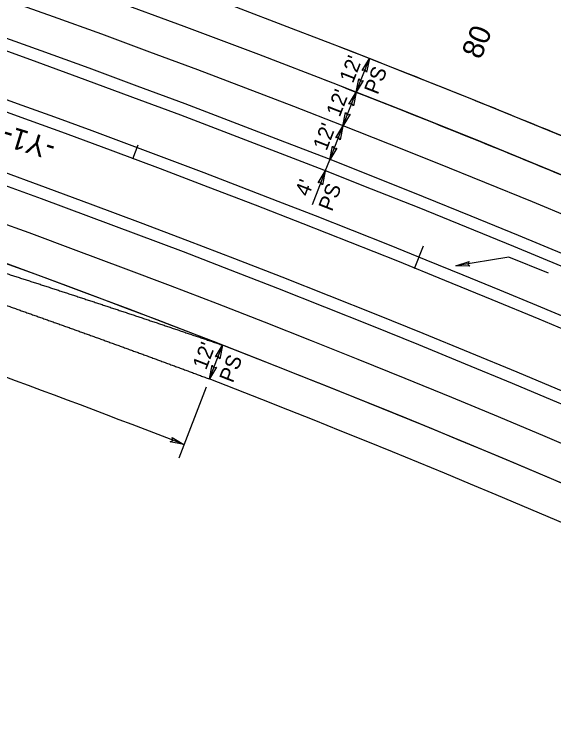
# Model space of a CAD drawing. Extents: x 2389694 to 2405615, y 547005 to 573532.
# Drawn here: x 2396125.1 to 2396303.6, y 553822.6 to 554061.5 of the extents above; entities that cross this region are included whole.
import ezdxf

# ---------------------------------------------------------------- set-up
doc = ezdxf.new("R2010")
doc.units = 0
for name, color, linetype in [('Prop Cable Guiderail Double Face', 7, 'Continuous'), ('Prop Dimension', 7, 'Continuous'), ('Prop Dimension Text', 7, 'Continuous'), ('Prop EOT', 7, 'Continuous'), ('Prop Horizontal Alignment', 7, 'Continuous'), ('Prop Horizontal Alignment Curve and Spiral Data', 7, 'Continuous'), ('Prop Horizontal Alignment Tick Large', 7, 'Continuous'), ('Prop Horizontal Alignment Tick Small', 7, 'Continuous'), ('Prop Lane Lines', 7, 'Continuous')]:
    doc.layers.add(name, color=color, linetype=linetype)

msp = doc.modelspace()

# ---------------------------------------------------------------- linework, layer by layer
at = {"layer": 'Prop Cable Guiderail Double Face'}
msp.add_arc((2394828.31, 550434.92), 3824, 59.69891, 72.33337, dxfattribs=at)
at = {"layer": 'Prop Dimension'}
for p, q in [((2396238.24, 554035.72), (2396242.62, 554046.89)), ((2396233.87, 554024.54), (2396238.24, 554035.72)), ((2396229.49, 554013.37), (2396233.87, 554024.54)), ((2396228.04, 554009.65), (2396229.49, 554013.37)), ((2396228.04, 554009.65), (2396223.65, 553998.44)), ((2396288.79, 553981.18), (2396271.28, 553978.28)), ((2396301.92, 553975.92), (2396288.79, 553981.18)), ((2396189.65, 553940.9), (2396193.99, 553952.08)), ((2396188.6, 553938.12), (2396179.52, 553914.73))]:
    msp.add_line(p, q, dxfattribs=at)
for points in [[(2396240.26, 554042.98), (2396242.62, 554046.89), (2396241.71, 554042.39), (2396241.18, 554043.21)], [(2396240.61, 554039.63), (2396238.24, 554035.72), (2396239.15, 554040.22), (2396239.69, 554039.4)], [(2396235.88, 554031.81), (2396238.24, 554035.72), (2396237.34, 554031.21), (2396236.8, 554032.04)], [(2396236.23, 554028.45), (2396233.87, 554024.54), (2396234.77, 554029.05), (2396235.31, 554028.22)], [(2396231.51, 554020.64), (2396233.87, 554024.54), (2396232.96, 554020.04), (2396232.43, 554020.87)], [(2396231.86, 554017.28), (2396229.49, 554013.37), (2396230.4, 554017.88), (2396230.93, 554017.05)], [(2396225.67, 554005.74), (2396228.04, 554009.65), (2396227.13, 554005.14), (2396226.6, 554005.97)], [(2396275.85, 553978.25), (2396271.28, 553978.28), (2396275.62, 553979.8), (2396275.18, 553978.92)], [(2396191.64, 553948.17), (2396193.99, 553952.08), (2396193.1, 553947.57), (2396192.56, 553948.4)], [(2396192, 553944.81), (2396189.65, 553940.9), (2396190.54, 553945.4), (2396191.07, 553944.58)], [(2396177.32, 553921.5), (2396181.24, 553919.17), (2396176.73, 553920.04), (2396177.55, 553920.58)]]:
    msp.add_lwpolyline(points, close=True, dxfattribs=at)
msp.add_arc((2394828.31, 550434.92), 3737.71, 68.77886, 73.27853, dxfattribs=at)
at = {"layer": 'Prop EOT'}
for centre, radius, start, end in [((2394828.31, 550434.92), 3879, 67.475, 106.78848), ((2396804.19, 554652.62), 768, 206.69831, 230.69056), ((2394828.31, 550434.92), 3867, 59.69891, 109.59769), ((2394828.31, 550434.92), 3843, 59.69891, 123.9393), ((2394828.31, 550434.92), 3839, 59.69891, 123.9393), ((2394828.31, 550434.92), 3801, 59.69891, 123.9393), ((2394828.31, 550434.92), 3797, 59.69891, 123.9393), ((2394828.31, 550434.92), 3879, 67.475, 68.77886), ((2394828.31, 550434.92), 3867, 67.475, 68.77886), ((2394828.31, 550434.92), 3773, 59.69891, 68.77934), ((2394828.31, 550434.92), 3761, 59.69891, 68.77934)]:
    msp.add_arc(centre, radius, start, end, dxfattribs=at)
for points in [[(2396081.28, 553988.7), (2396082.04, 553988.47), (2396082.81, 553988.23), (2396083.57, 553988), (2396084.34, 553987.76), (2396085.1, 553987.53), (2396085.87, 553987.29), (2396086.64, 553987.05), (2396087.4, 553986.81), (2396088.17, 553986.58), (2396088.93, 553986.34), (2396089.69, 553986.1), (2396090.46, 553985.87), (2396091.22, 553985.63), (2396091.99, 553985.39), (2396092.75, 553985.15), (2396093.51, 553984.92), (2396094.28, 553984.68), (2396095.04, 553984.44), (2396095.81, 553984.2), (2396096.58, 553983.96), (2396097.34, 553983.72), (2396098.1, 553983.48), (2396098.87, 553983.25), (2396099.63, 553983.01), (2396100.39, 553982.77), (2396101.16, 553982.53), (2396101.92, 553982.29), (2396102.68, 553982.05), (2396103.45, 553981.81), (2396104.21, 553981.57), (2396104.98, 553981.33), (2396105.74, 553981.09), (2396106.51, 553980.84), (2396107.27, 553980.6), (2396108.03, 553980.36), (2396108.8, 553980.12), (2396109.56, 553979.88), (2396110.32, 553979.64), (2396111.08, 553979.4), (2396111.85, 553979.16), (2396112.61, 553978.92), (2396113.37, 553978.67), (2396114.13, 553978.43), (2396114.91, 553978.19), (2396115.67, 553977.94), (2396116.43, 553977.7), (2396117.19, 553977.46), (2396117.95, 553977.22), (2396118.72, 553976.97), (2396119.48, 553976.73), (2396120.24, 553976.49), (2396121, 553976.24), (2396121.76, 553976), (2396122.53, 553975.75), (2396123.29, 553975.51), (2396124.06, 553975.26), (2396124.82, 553975.02), (2396125.58, 553974.77), (2396126.35, 553974.53), (2396127.11, 553974.28), (2396127.87, 553974.04), (2396128.63, 553973.79), (2396129.39, 553973.55), (2396130.15, 553973.3), (2396130.91, 553973.06), (2396131.68, 553972.81), (2396132.44, 553972.57), (2396133.21, 553972.32), (2396133.97, 553972.07), (2396134.73, 553971.82), (2396135.49, 553971.58), (2396136.25, 553971.33), (2396137.01, 553971.08), (2396137.77, 553970.84)], [(2396078.35, 553980.4), (2396079.11, 553980.15), (2396079.86, 553979.89), (2396080.62, 553979.64), (2396081.37, 553979.38), (2396082.13, 553979.13), (2396082.89, 553978.87), (2396083.65, 553978.61), (2396084.4, 553978.36), (2396085.16, 553978.1), (2396085.91, 553977.84), (2396086.67, 553977.59), (2396087.42, 553977.33), (2396088.18, 553977.07), (2396088.93, 553976.82), (2396089.69, 553976.56), (2396090.44, 553976.3), (2396091.2, 553976.04), (2396091.95, 553975.79), (2396092.72, 553975.53), (2396093.47, 553975.27), (2396094.22, 553975.01), (2396094.98, 553974.75), (2396095.73, 553974.49), (2396096.49, 553974.23), (2396097.24, 553973.97), (2396097.99, 553973.72), (2396098.75, 553973.46), (2396099.5, 553973.2), (2396100.26, 553972.94), (2396101.01, 553972.68), (2396101.77, 553972.42), (2396102.53, 553972.16), (2396103.28, 553971.9), (2396104.03, 553971.64), (2396104.79, 553971.37), (2396105.54, 553971.11), (2396106.29, 553970.85), (2396107.05, 553970.59), (2396107.8, 553970.33), (2396108.56, 553970.07), (2396109.31, 553969.81), (2396110.06, 553969.55), (2396110.81, 553969.29), (2396111.58, 553969.02), (2396112.33, 553968.76), (2396113.08, 553968.5), (2396113.84, 553968.23), (2396114.59, 553967.97), (2396115.34, 553967.71), (2396116.09, 553967.45), (2396116.85, 553967.18), (2396117.6, 553966.92), (2396118.35, 553966.66), (2396119.1, 553966.39), (2396119.86, 553966.13), (2396120.62, 553965.86), (2396121.37, 553965.6), (2396122.12, 553965.33), (2396122.88, 553965.07), (2396123.63, 553964.81), (2396124.38, 553964.54), (2396125.13, 553964.28), (2396125.88, 553964.01), (2396126.64, 553963.75), (2396127.39, 553963.48), (2396128.14, 553963.22), (2396128.89, 553962.95), (2396129.65, 553962.68), (2396130.41, 553962.41), (2396131.16, 553962.15), (2396131.91, 553961.88), (2396132.66, 553961.62), (2396133.41, 553961.35), (2396134.16, 553961.08)], [(2396137.77, 553970.84), (2396138.54, 553970.59), (2396139.3, 553970.34), (2396140.06, 553970.09), (2396140.82, 553969.85), (2396141.58, 553969.6), (2396142.34, 553969.35), (2396143.11, 553969.1), (2396143.87, 553968.85), (2396144.63, 553968.6), (2396145.39, 553968.35), (2396146.15, 553968.1), (2396146.91, 553967.85), (2396147.67, 553967.6), (2396148.43, 553967.35), (2396149.19, 553967.1), (2396149.95, 553966.86), (2396150.71, 553966.61), (2396151.48, 553966.36), (2396152.24, 553966.1), (2396153, 553965.85), (2396153.77, 553965.6), (2396154.52, 553965.35), (2396155.29, 553965.1), (2396156.04, 553964.85), (2396156.8, 553964.6), (2396157.56, 553964.34), (2396158.32, 553964.09), (2396159.08, 553963.84), (2396159.84, 553963.59), (2396160.6, 553963.34), (2396161.37, 553963.08), (2396162.13, 553962.83), (2396162.89, 553962.58), (2396163.65, 553962.32), (2396164.41, 553962.07), (2396165.17, 553961.82), (2396165.93, 553961.57), (2396166.69, 553961.31), (2396167.45, 553961.06), (2396168.21, 553960.8), (2396168.97, 553960.55), (2396169.72, 553960.3), (2396170.48, 553960.04), (2396171.25, 553959.78), (2396172.01, 553959.53), (2396172.77, 553959.28), (2396173.53, 553959.02), (2396174.29, 553958.77), (2396175.05, 553958.51), (2396175.81, 553958.25), (2396176.56, 553958), (2396177.32, 553957.74), (2396178.08, 553957.49), (2396178.84, 553957.23), (2396179.6, 553956.98), (2396180.37, 553956.72), (2396181.12, 553956.46), (2396181.88, 553956.2), (2396182.64, 553955.95), (2396183.4, 553955.69), (2396184.16, 553955.43), (2396184.92, 553955.17), (2396185.67, 553954.92), (2396186.43, 553954.66), (2396187.19, 553954.4), (2396187.95, 553954.14), (2396188.71, 553953.89), (2396189.47, 553953.62), (2396190.23, 553953.36), (2396190.99, 553953.11), (2396191.75, 553952.85), (2396192.5, 553952.59), (2396194.02, 553952.07)], [(2396134.16, 553961.08), (2396134.91, 553960.82), (2396135.67, 553960.55), (2396136.42, 553960.28), (2396137.17, 553960.01), (2396137.92, 553959.75), (2396138.67, 553959.48), (2396139.43, 553959.21), (2396140.18, 553958.94), (2396140.93, 553958.67), (2396141.68, 553958.4), (2396142.44, 553958.14), (2396143.19, 553957.87), (2396143.94, 553957.6), (2396144.69, 553957.33), (2396145.44, 553957.06), (2396146.19, 553956.79), (2396146.94, 553956.52), (2396147.69, 553956.25), (2396148.45, 553955.98), (2396149.2, 553955.71), (2396149.95, 553955.44), (2396150.7, 553955.17), (2396151.45, 553954.9), (2396152.2, 553954.63), (2396152.95, 553954.36), (2396153.7, 553954.09), (2396154.45, 553953.82), (2396155.2, 553953.54), (2396155.95, 553953.27), (2396156.7, 553953), (2396157.46, 553952.73), (2396158.21, 553952.45), (2396158.96, 553952.18), (2396159.71, 553951.91), (2396160.46, 553951.64), (2396161.21, 553951.37), (2396161.96, 553951.09), (2396162.71, 553950.82), (2396163.46, 553950.55), (2396164.21, 553950.27), (2396164.95, 553950), (2396165.7, 553949.73), (2396166.45, 553949.45), (2396167.21, 553949.18), (2396167.96, 553948.9), (2396168.71, 553948.63), (2396169.46, 553948.35), (2396170.21, 553948.08), (2396170.96, 553947.81), (2396171.7, 553947.53), (2396172.45, 553947.26), (2396173.2, 553946.98), (2396173.95, 553946.71), (2396174.7, 553946.43), (2396175.45, 553946.16), (2396176.2, 553945.88), (2396176.95, 553945.6), (2396177.7, 553945.32), (2396178.45, 553945.05), (2396179.2, 553944.77), (2396179.95, 553944.5), (2396180.69, 553944.22), (2396181.44, 553943.94), (2396182.19, 553943.67), (2396182.94, 553943.39), (2396183.68, 553943.11), (2396184.43, 553942.83), (2396185.19, 553942.55), (2396185.94, 553942.27), (2396186.68, 553942), (2396187.43, 553941.72), (2396188.18, 553941.44), (2396189.67, 553940.88)]]:
    msp.add_spline(points, degree=3, dxfattribs=at)
at = {"layer": 'Prop Horizontal Alignment'}
msp.add_arc((2394828.31, 550434.92), 3820, 59.69891, 123.9393, dxfattribs=at)
at = {"layer": 'Prop Horizontal Alignment Tick Large'}
msp.add_line((2396257.52, 553977.48), (2396260.51, 553984.9), dxfattribs=at)
at = {"layer": 'Prop Horizontal Alignment Tick Small'}
msp.add_line((2396164.3, 554013.68), (2396166.05, 554018.36), dxfattribs=at)
at = {"layer": 'Prop Lane Lines'}
for radius, start, end in [(3855, 59.69891, 123.9393), (3785, 59.69891, 123.9393), (3773, 68.81433, 89.07696), (3773, 59.69891, 88.86914)]:
    msp.add_arc((2394828.31, 550434.92), radius, start, end, dxfattribs=at)

# ---------------------------------------------------------------- texts
at = {"layer": 'Prop Dimension Text'}
for s, rotation, p in [("12'", 68.6169, (2396237.17, 554038.46)), ('PS', 68.6169, (2396245.36, 554034.7)), ("12'", 68.6169, (2396232.8, 554027.29)), ("12'", 68.6169, (2396228.42, 554016.11)), ("4'", 68.6171, (2396222.48, 554000.95)), ('PS', 68.6171, (2396230.23, 553996.06)), ("12'", 68.7795, (2396188.56, 553943.63)), ('PS', 68.6171, (2396197.41, 553939.32))]:
    msp.add_text(s, height=5, rotation=rotation, dxfattribs=at).set_placement(p)
at = {"layer": 'Prop Horizontal Alignment Curve and Spiral Data'}
for s, rotation, p in [('80', 68.0289, (2396279.46, 554046.31)), ('-Y1-', 162.9204, (2396139.3, 554019.87))]:
    msp.add_text(s, height=7, rotation=rotation, dxfattribs=at).set_placement(p)

doc.saveas('drawing.dxf')
